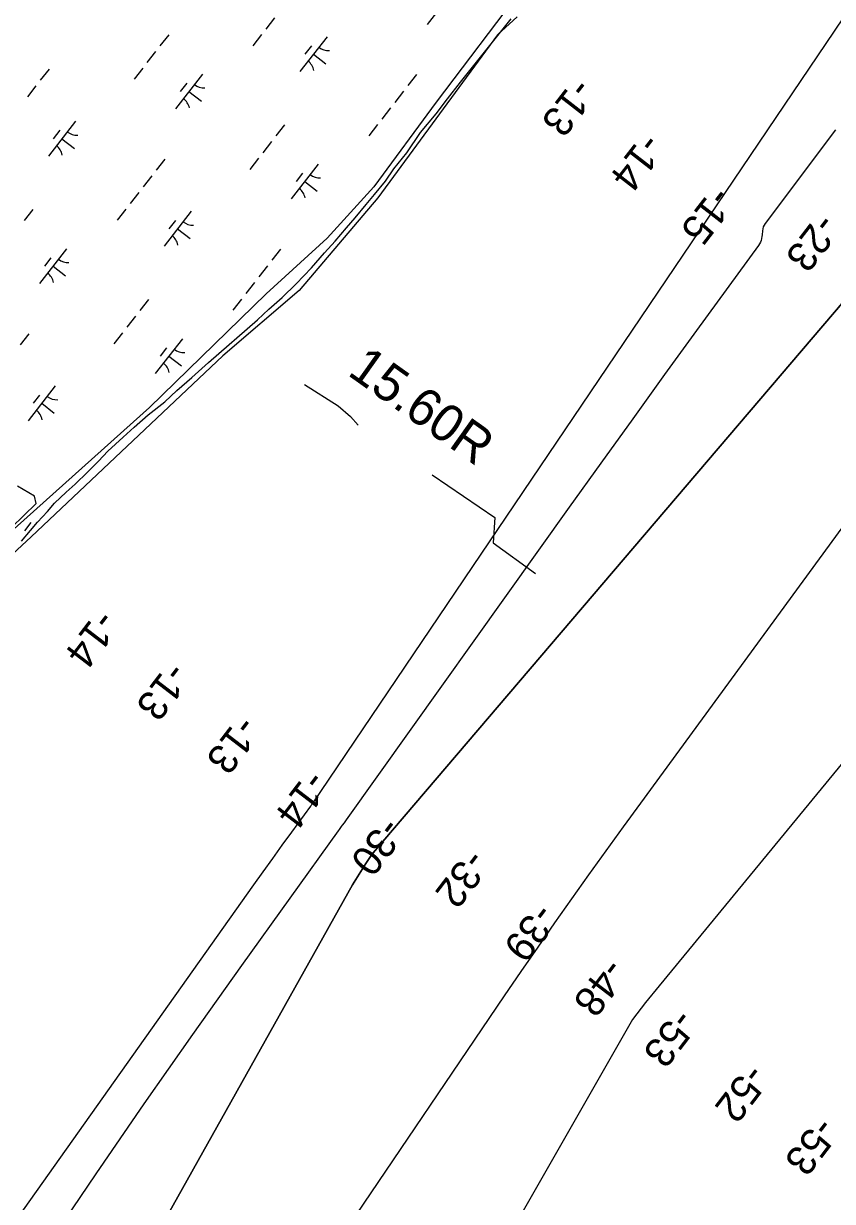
# Model space of a CAD drawing. Extents: x 3888273 to 3909528, y 158682 to 181032.
# Drawn here: x 3901471 to 3902388, y 172716 to 174052 of the extents above; entities that cross this region are included whole.
import ezdxf

# ---------------------------------------------------------------- set-up
doc = ezdxf.new("R2010")
doc.units = 0
for name, color, linetype in [('V-LEVE-TOET', 7, 'Continuous'), ('V-RIVR-EDGE', 7, 'Continuous'), ('V-RIVR-RANG', 7, 'Continuous'), ('V-RRAP-FSHR', 7, 'Continuous'), ('V-STRM-FMON', 7, 'Continuous'), ('V-TOPO-DPTH', 7, 'Continuous'), ('V-TOPO-MAJR', 7, 'Continuous'), ('V-TOPO-MINR', 7, 'Continuous'), ('V-WETL-SWMP', 7, 'Continuous')]:
    doc.layers.add(name, color=color, linetype=linetype)

msp = doc.modelspace()

# ---------------------------------------------------------------- linework, layer by layer
at = {"layer": 'V-LEVE-TOET'}
for points in [[(3901789.5, 173642.3), (3901827.5, 173618), (3901841.5, 173605.9), (3901850.3, 173596)], [(3901934.3, 173539.7), (3902005.1, 173491.2), (3902003.5, 173462.6), (3902051.5, 173427.8)]]:
    msp.add_lwpolyline(points, dxfattribs=at)
at = {"layer": 'V-RIVR-EDGE'}
for points in [[(3902030.5, 174059.3), (3902008.2, 174038.9), (3901872.5, 173854), (3901783.3, 173749), (3901696.9, 173674.6), (3901479.5, 173469.3), (3901346.6, 173346.6)], [(3901358.7, 173384.7), (3901485.1, 173507.4), (3901483.2, 173515.7), (3901463.7, 173526.9)]]:
    msp.add_lwpolyline(points, dxfattribs=at)
at = {"layer": 'V-RRAP-FSHR'}
msp.add_lwpolyline([(3903102.7, 175509.3), (3903082.1, 175483.4), (3902997.5, 175371.3), (3902864.9, 175197.8), (3902673.3, 174922.4), (3902531.8, 174738.4), (3902438.3, 174619.4), (3902219.3, 174329.8), (3902036.5, 174092.1), (3901938.6, 173962.6), (3901868.1, 173866.6), (3901815, 173808.1), (3901746, 173745.2), (3901613.7, 173616.3), (3901452.9, 173472.2), (3901199.6, 173252.1), (3901151.7, 173210), (3901101.4, 173147), (3901045.8, 173104.6), (3901042.7, 173100.6), (3901016.7, 173085.3)], dxfattribs=at)
at = {"layer": 'V-TOPO-DPTH'}
for points in [[(3902391.5, 173931.1), (3902311.7, 173825), (3902309.7, 173821.1), (3902308.8, 173816.7), (3902308.5, 173812.2), (3902308.2, 173810), (3902307.2, 173805.7), (3902306.4, 173803.6), (3902304.2, 173799.8), (3902234.1, 173703.5), (3902197.8, 173653.5), (3902161.6, 173603.4), (3902125.5, 173553.2), (3902089.6, 173503), (3901836.6, 173148.3), (3901834.4, 173145.2), (3901832.1, 173142.2), (3901831, 173140.7), (3901828.8, 173137.6), (3901827.7, 173136.1), (3901717.9, 172983.1), (3901662.3, 172904.8), (3901607.2, 172826.2), (3901552.8, 172747), (3901498.9, 172667.6)], [(3900896.8, 171591.3), (3901374.6, 172277.6), (3901392.1, 172302.5), (3901409.7, 172327.5), (3901427.4, 172352.3), (3901445.2, 172377), (3901481, 172426.3), (3901481, 172426.3), (3901481.3, 172426.8), (3901481.3, 172426.9), (3901843.9, 173074.5), (3901847.5, 173080.7), (3901851.2, 173086.9), (3901855, 173093), (3901858.9, 173099), (3901866.4, 173110.3), (3901866.6, 173110.6), (3901866.9, 173110.8), (3901867.2, 173110.8), (3902412.3, 173749.9)], [(3900896.8, 171591.3), (3901374.6, 172277.6), (3901392.1, 172302.5), (3901409.7, 172327.5), (3901427.4, 172352.3), (3901445.2, 172377), (3901481, 172426.3), (3901481, 172426.3), (3901481.3, 172426.8), (3901481.3, 172426.9), (3901843.9, 173074.5), (3901847.5, 173080.7), (3901851.2, 173086.9), (3901855, 173093), (3901858.9, 173099), (3901866.4, 173110.3), (3901866.6, 173110.6), (3901866.9, 173110.8), (3901867.2, 173110.8), (3902412.3, 173749.9)], [(3902512.8, 173635.7), (3902170.5, 173167.4), (3902150.8, 173140.4), (3902131.1, 173113.3), (3902111.6, 173086.1), (3902092.2, 173058.8), (3902072.9, 173031.4), (3902053.8, 173004), (3902034.8, 172976.4), (3902015.9, 172948.8), (3901839.1, 172687.9), (3901799.1, 172629.4), (3901758.8, 172571), (3901718.2, 172513), (3901677.3, 172455.1), (3901618, 172372), (3901606.5, 172355.9), (3901594.8, 172339.8), (3901583.1, 172323.9), (3901571.2, 172308), (3901457.7, 172156.8), (3901389.3, 172065.2), (3901321.2, 171973.3), (3901253.5, 171881.1)], [(3902512.8, 173635.7), (3902170.5, 173167.4), (3902150.8, 173140.4), (3902131.1, 173113.3), (3902111.6, 173086.1), (3902092.2, 173058.8), (3902072.9, 173031.4), (3902053.8, 173004), (3902034.8, 172976.4), (3902015.9, 172948.8), (3901839.1, 172687.9), (3901799.1, 172629.4), (3901758.8, 172571), (3901718.2, 172513), (3901677.3, 172455.1), (3901618, 172372), (3901606.5, 172355.9), (3901594.8, 172339.8), (3901583.1, 172323.9), (3901571.2, 172308), (3901457.7, 172156.8), (3901389.3, 172065.2), (3901321.2, 171973.3), (3901253.5, 171881.1)]]:
    msp.add_lwpolyline(points, dxfattribs=at)
at = {"layer": 'V-TOPO-MAJR'}
msp.add_lwpolyline([(3902478.5, 173309.1), (3902191.5, 172960.1), (3902176.2, 172941.1), (3902161.3, 172921.8), (3901779.2, 172252.9), (3901113.4, 171476.9)], dxfattribs=at)
at = {"layer": 'V-TOPO-MINR'}
for points in [[(3902629.3, 174397.8), (3901798, 173166.4), (3901797.8, 173166.1), (3901796.9, 173164.8), (3901796.2, 173163.9), (3901774.7, 173134.6), (3901763.8, 173119.6), (3901752.9, 173104.6), (3901742.1, 173089.6), (3901731.4, 173074.5), (3901333.6, 172514.1), (3901333.3, 172513.7), (3901332.3, 172512.3), (3901331.6, 172511.3), (3901299.3, 172466), (3901282.8, 172443), (3901266.3, 172420.1), (3901249.7, 172397.2), (3901233, 172374.4), (3900716.6, 171670.4)], [(3902391.5, 173931.1), (3902311.7, 173825), (3902309.7, 173821.1), (3902308.8, 173816.7), (3902308.5, 173812.2), (3902308.2, 173810), (3902307.2, 173805.7), (3902306.4, 173803.6), (3902304.2, 173799.8), (3902234.1, 173703.5), (3902197.8, 173653.5), (3902161.6, 173603.4), (3902125.5, 173553.2), (3902089.6, 173503), (3901836.6, 173148.3), (3901834.4, 173145.2), (3901832.1, 173142.2), (3901831, 173140.7), (3901828.8, 173137.6), (3901827.7, 173136.1), (3901717.9, 172983.1), (3901662.3, 172904.8), (3901607.2, 172826.2), (3901552.8, 172747), (3901498.9, 172667.6)], [(3902412.3, 173749.9), (3901867.2, 173110.8), (3901866.9, 173110.8), (3901866.6, 173110.6), (3901866.4, 173110.3), (3901858.9, 173099), (3901855, 173093), (3901851.2, 173086.9), (3901847.5, 173080.7), (3901843.9, 173074.5), (3901481.3, 172426.9), (3901481.3, 172426.8), (3901481, 172426.3), (3901481, 172426.3), (3901445.2, 172377), (3901427.4, 172352.3), (3901409.7, 172327.5), (3901392.1, 172302.5), (3901374.6, 172277.6), (3900896.8, 171591.3)], [(3902512.8, 173635.7), (3902170.5, 173167.4), (3902150.8, 173140.4), (3902131.1, 173113.3), (3902111.6, 173086.1), (3902092.2, 173058.8), (3902072.9, 173031.4), (3902053.8, 173004), (3902034.8, 172976.4), (3902015.9, 172948.8), (3901839.1, 172687.9), (3901799.1, 172629.4), (3901758.8, 172571), (3901718.2, 172513), (3901677.3, 172455.1), (3901618, 172372), (3901606.5, 172355.9), (3901594.8, 172339.8), (3901583.1, 172323.9), (3901571.2, 172308), (3901457.7, 172156.8), (3901389.3, 172065.2), (3901321.2, 171973.3), (3901253.5, 171881.1)]]:
    msp.add_lwpolyline(points, dxfattribs=at)
at = {"layer": 'V-WETL-SWMP'}
for p, q in [((3901959, 174090.2), (3901928.3, 174050.7)), ((3901755.5, 174058.1), (3901745.6, 174045.5)), ((3901966.4, 173985.1), (3902023.9, 174057)), ((3901635.3, 174039), (3901625.4, 174026.3)), ((3901740.7, 174039.2), (3901730.9, 174026.6)), ((3901814.9, 174036.7), (3901784.2, 173997.3)), ((3901797.1, 174026.5), (3901789.7, 174017)), ((3901620.5, 174020), (3901610.7, 174007.4)), ((3901799.5, 174017), (3901813.7, 174005.9)), ((3901499.6, 174000.1), (3901489.7, 173987.5)), ((3901605.8, 174001.1), (3901596, 173988.5)), ((3901673.6, 173994.3), (3901642.9, 173954.8)), ((3901655.9, 173984), (3901648.5, 173974.6)), ((3901916.2, 173993.9), (3901906.4, 173981.3)), ((3901951.5, 173966.3), (3901966.4, 173985.1)), ((3901484.8, 173981.2), (3901475, 173968.5)), ((3901658.3, 173974.6), (3901672.5, 173963.5)), ((3901901.5, 173974.9), (3901891.7, 173962.3)), ((3901886.7, 173956), (3901876.9, 173943.4)), ((3901938.6, 173949.2), (3901951.5, 173966.3)), ((3901921, 173928), (3901938.6, 173949.2)), ((3901529.5, 173940.8), (3901498.8, 173901.4)), ((3901511.7, 173930.6), (3901504.4, 173921.1)), ((3901766.5, 173936.8), (3901756.7, 173924.2)), ((3901872, 173937.1), (3901862.2, 173924.4)), ((3901514.1, 173921.1), (3901528.3, 173910)), ((3901751.8, 173917.9), (3901742, 173905.2)), ((3901905.4, 173904.9), (3901921, 173928)), ((3901890.6, 173886.9), (3901905.4, 173904.9)), ((3901630.8, 173898), (3901621, 173885.3)), ((3901737.1, 173898.9), (3901727.2, 173886.3)), ((3901804.9, 173892.1), (3901774.2, 173852.7)), ((3901616.1, 173879), (3901606.3, 173866.4)), ((3901787.2, 173881.9), (3901779.8, 173872.4)), ((3901881.2, 173872.9), (3901890.6, 173886.9)), ((3901789.6, 173872.4), (3901803.8, 173861.4)), ((3901868.7, 173857.7), (3901881.2, 173872.9)), ((3901601.4, 173860.1), (3901591.5, 173847.5)), ((3901859.3, 173846.5), (3901868.7, 173857.7)), ((3901481.2, 173840.9), (3901471.3, 173828.3)), ((3901586.6, 173841.1), (3901576.8, 173828.5)), ((3901660.8, 173838.7), (3901630.1, 173799.2)), ((3901846.8, 173831.3), (3901859.3, 173846.5)), ((3901643, 173828.4), (3901635.6, 173818.9)), ((3901837, 173819.8), (3901846.8, 173831.3)), ((3901645.4, 173818.9), (3901659.6, 173807.9)), ((3901824.1, 173805), (3901837, 173819.8)), ((3901519.5, 173796.2), (3901488.8, 173756.8)), ((3901762.1, 173795.8), (3901752.3, 173783.2)), ((3901811.9, 173791.8), (3901824.1, 173805)), ((3901501.8, 173786), (3901494.4, 173776.5)), ((3901797.1, 173774.6), (3901811.9, 173791.8)), ((3901504.2, 173776.5), (3901518.4, 173765.4)), ((3901747.4, 173776.9), (3901737.6, 173764.3)), ((3901779.8, 173756.6), (3901797.1, 173774.6)), ((3901732.6, 173757.9), (3901722.8, 173745.3)), ((3901764.1, 173740.9), (3901779.8, 173756.6)), ((3901612.4, 173738.8), (3901602.6, 173726.1)), ((3901717.9, 173739), (3901708.1, 173726.4)), ((3901748.8, 173727.7), (3901764.1, 173740.9)), ((3901597.7, 173719.8), (3901587.9, 173707.2)), ((3901680.5, 173667.2), (3901735.9, 173715.7)), ((3901735.9, 173715.7), (3901748.8, 173727.7)), ((3901476.7, 173699.9), (3901466.9, 173687.3)), ((3901583, 173700.9), (3901573.1, 173688.2)), ((3901650.8, 173694.1), (3901620.1, 173654.6)), ((3901633, 173683.8), (3901625.7, 173674.3)), ((3901635.4, 173674.3), (3901649.7, 173663.3)), ((3901661.7, 173650.3), (3901680.5, 173667.2)), ((3901644.4, 173635.5), (3901661.7, 173650.3)), ((3901506.7, 173640.6), (3901476, 173601.1)), ((3901631.1, 173622.7), (3901644.4, 173635.5)), ((3901488.9, 173630.3), (3901481.5, 173620.9)), ((3901612.2, 173607.8), (3901631.1, 173622.7)), ((3901491.3, 173620.9), (3901505.5, 173609.8)), ((3901596.1, 173593.8), (3901612.2, 173607.8)), ((3901566.3, 173566.5), (3901583.6, 173582.6)), ((3901583.6, 173582.6), (3901596.1, 173593.8)), ((3901543.2, 173542.9), (3901555.7, 173555.3)), ((3901555.7, 173555.3), (3901566.3, 173566.5)), ((3901529.1, 173529.3), (3901543.2, 173542.9)), ((3901518.9, 173520.1), (3901529.1, 173529.3)), ((3901505.9, 173507.7), (3901518.9, 173520.1)), ((3901497.7, 173498.1), (3901505.9, 173507.7)), ((3901486.7, 173486.1), (3901497.7, 173498.1)), ((3901468.3, 173464.5), (3901478.5, 173476.5)), ((3901478.9, 173485.8), (3901471.6, 173476.3)), ((3901478.5, 173476.5), (3901486.7, 173486.1))]:
    msp.add_line(p, q, dxfattribs=at)
for centre, start, end in [((3901816.7, 174038.7), 231.343, 272.8866), ((3901782.7, 173995.1), 11.343, 52.8866), ((3901675.4, 173996.2), 231.343, 272.8866), ((3901641.5, 173952.6), 11.343, 52.8866), ((3901531.3, 173942.7), 231.343, 272.8866), ((3901497.4, 173899.1), 11.343, 52.8866), ((3901806.7, 173894.1), 231.343, 272.8866), ((3901772.8, 173850.5), 11.343, 52.8866), ((3901662.6, 173840.6), 231.343, 272.8866), ((3901628.6, 173797), 11.343, 52.8866), ((3901521.3, 173798.1), 231.343, 272.8866), ((3901487.4, 173754.5), 11.343, 52.8866), ((3901652.6, 173696), 231.343, 272.8866), ((3901618.7, 173652.4), 11.343, 52.8866), ((3901508.5, 173642.5), 231.343, 272.8866), ((3901474.5, 173598.9), 11.343, 52.8866)]:
    msp.add_arc(centre, 17.6, start, end, dxfattribs=at)

# ---------------------------------------------------------------- texts
at = {"layer": 'V-RIVR-RANG'}
for s, rotation, p in [('-13', 232.1983, (3902096.3, 173992.1)), ('-14', 232.1983, (3902174.4, 173929.6)), ('-15', 232.1983, (3902254.1, 173869.3)), ('-23', 232.3354, (3902373, 173838.7)), ('-14', 232.5083, (3901555.8, 173388.9)), ('-13', 232.5083, (3901636.3, 173329.6)), ('-13', 232.5083, (3901715.8, 173268.9)), ('-14', 232.5083, (3901794.3, 173206.9)), ('-30', 232.5083, (3901879.4, 173153.6)), ('-32', 232.6536, (3901975.4, 173117.2)), ('-39', 232.6536, (3902052.9, 173056.1)), ('-48', 232.6536, (3902132, 172993.8)), ('-53', 232.6536, (3902211.3, 172936.2)), ('-52', 232.6536, (3902292.5, 172873.8)), ('-53', 232.6536, (3902371.6, 172813.6))]:
    msp.add_text(s, height=33.5, rotation=rotation, dxfattribs=at).set_placement(p)
at = {"layer": 'V-STRM-FMON'}
msp.add_text('15.60R', height=42, rotation=324.6085, dxfattribs=at).set_placement((3901836.8, 173653.9))

doc.saveas('drawing.dxf')
